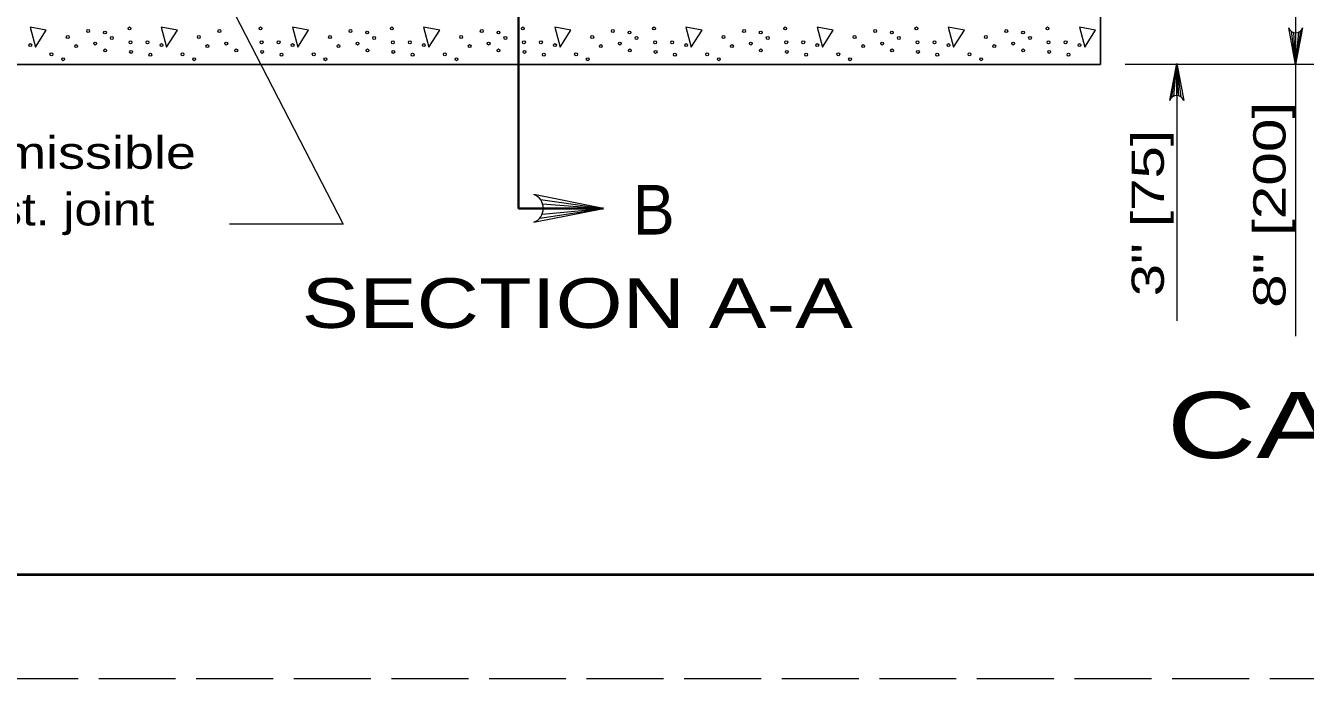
# Model space of a CAD drawing. Extents: x 1329.9 to 1363.9, y 715.5 to 737.5.
# Drawn here: x 1333.29 to 1339.48, y 715.5 to 718.65 of the extents above; entities that cross this region are included whole.
import ezdxf
from ezdxf.enums import TextEntityAlignment as Align

# ---------------------------------------------------------------- set-up
doc = ezdxf.new("R2010")
doc.units = 0
doc.header["$LTSCALE"] = 0.062
doc.linetypes.add('LONG_DASHED', pattern=[7.5, 6, -1.5])
doc.layers.add('1', color=7, linetype='Continuous', lineweight=13)

msp = doc.modelspace()

# ---------------------------------------------------------------- linework, layer by layer
at = {"layer": '1', "lineweight": 25}
for p, q in [((1338.4845, 718.46475), (1338.4845, 722.27233)), ((1332.86792, 718.46475), (1338.4845, 718.46475))]:
    msp.add_line(p, q, dxfattribs=at)
at = {"layer": '1', "lineweight": 35}
for p in [(1335.66942, 720.78442), (1336.08058, 717.76983)]:
    msp.add_line(p, (1335.66942, 717.76983), dxfattribs=at)
at = {"layer": '1'}
for p, q in [((1339.42875, 719.1235), (1339.42875, 717.1515)), ((1339.40742, 718.626), (1339.42875, 718.46475)), ((1339.41792, 718.6205), (1339.42875, 718.46475)), ((1339.45225, 718.62783), (1339.42875, 718.46475)), ((1339.44242, 718.62167), (1339.42875, 718.46475)), ((1339.42875, 718.61883), (1339.42875, 718.46475)), ((1340.42842, 718.46475), (1338.60475, 718.46475)), ((1338.83033, 718.30683), (1338.85383, 718.47)), ((1338.84017, 718.313), (1338.85383, 718.47)), ((1338.85383, 718.47), (1338.85383, 717.22583)), ((1338.85383, 718.31583), (1338.85383, 718.47)), ((1338.86458, 718.31417), (1338.85383, 718.47)), ((1338.87517, 718.30875), (1338.85383, 718.47)), ((1335.77242, 717.72275), (1336.08058, 717.76983)), ((1335.776, 717.8125), (1336.08058, 717.76983)), ((1335.78408, 717.7425), (1336.08058, 717.76983)), ((1335.78633, 717.79142), (1336.08058, 717.76983)), ((1335.7895, 717.76983), (1336.08058, 717.76983))]:
    msp.add_line(p, q, dxfattribs=at)
at = {"layer": '1', "linetype": 'LONG_DASHED'}
msp.add_lwpolyline([(1329.86333, 715.4975), (1363.86333, 715.4975), (1363.86333, 737.4975), (1329.86333, 737.4975)], close=True, dxfattribs=at)
at = {"layer": '1', "lineweight": 25}
msp.add_lwpolyline([(1363.36333, 715.9975), (1331.86333, 715.9975), (1331.86333, 736.9975)], dxfattribs=at)
at = {"layer": '1', "lineweight": 40}
msp.add_lwpolyline([(1331.86333, 736.9975), (1363.36333, 736.9975), (1363.36333, 715.9975), (1331.86333, 715.9975)], close=True, dxfattribs=at)
msp.add_lwpolyline([(1331.86333, 736.9975), (1363.36333, 736.9975), (1363.36333, 715.9975), (1331.86333, 715.9975)], close=True, dxfattribs=at)
at = {"layer": '1'}
for points in [[(1334.08708, 719.11958), (1334.82208, 717.69408), (1334.27158, 717.69408)], [(1339.46233, 718.64283), (1339.42875, 718.46475), (1339.39508, 718.64283)], [(1338.82025, 718.29183), (1338.85383, 718.47), (1338.8875, 718.29183)], [(1335.74417, 717.70258), (1336.08058, 717.76983), (1335.74417, 717.83717)]]:
    msp.add_lwpolyline(points, dxfattribs=at)
for points in [[(1333.30758, 718.64667), (1333.33325, 718.54925), (1333.3855, 718.63142)], [(1333.94208, 718.64667), (1333.96767, 718.54925), (1334.01992, 718.63142)], [(1334.57642, 718.64667), (1334.60208, 718.54925), (1334.65433, 718.63142)], [(1335.21083, 718.64667), (1335.23642, 718.54925), (1335.28867, 718.63142)], [(1335.84525, 718.64667), (1335.87092, 718.54925), (1335.92308, 718.63142)], [(1336.47967, 718.64667), (1336.50525, 718.54925), (1336.5575, 718.63142)], [(1337.114, 718.64667), (1337.13967, 718.54925), (1337.19192, 718.63142)], [(1337.74842, 718.64667), (1337.774, 718.54925), (1337.82633, 718.63142)], [(1338.38283, 718.64667), (1338.4085, 718.54925), (1338.46067, 718.63142)]]:
    msp.add_lwpolyline(points, close=True, dxfattribs=at)
msp.add_arc((1335.717, 717.76992), 0.07261, 292.08605, 67.91218, dxfattribs=at)
for centre in [(1333.58861, 718.62726), (1333.78792, 718.63991), (1334.22301, 718.62726), (1334.42232, 718.63991), (1334.85741, 718.62726), (1335.05672, 718.63991), (1335.49181, 718.62726), (1335.69111, 718.63991), (1336.12621, 718.62726), (1336.32551, 718.63991), (1336.7606, 718.62726), (1336.95991, 718.63991), (1337.395, 718.62726), (1337.59431, 718.63991), (1338.0294, 718.62726), (1338.22871, 718.63991), (1333.48927, 718.59821), (1333.62202, 718.56647), (1333.66944, 718.62026), (1333.70312, 718.59368), (1333.79305, 718.5728), (1333.87531, 718.5728), (1334.12367, 718.59821), (1334.25642, 718.56647), (1334.42744, 718.5728), (1334.50971, 718.5728), (1334.75807, 718.59821), (1334.89082, 718.56647), (1334.93824, 718.62026), (1334.97192, 718.59368), (1335.06184, 718.5728), (1335.1441, 718.5728), (1335.39247, 718.59821), (1335.52522, 718.56647), (1335.57264, 718.62026), (1335.60632, 718.59368), (1335.69624, 718.5728), (1335.7785, 718.5728), (1336.02687, 718.59821), (1336.15962, 718.56647), (1336.20704, 718.62026), (1336.24071, 718.59368), (1336.33064, 718.5728), (1336.4129, 718.5728), (1336.66127, 718.59821), (1336.79402, 718.56647), (1336.84144, 718.62026), (1336.87511, 718.59368), (1336.96504, 718.5728), (1337.0473, 718.5728), (1337.29567, 718.59821), (1337.42841, 718.56647), (1337.47584, 718.62026), (1337.50951, 718.59368), (1337.59944, 718.5728), (1337.6817, 718.5728), (1337.93007, 718.59821), (1338.06281, 718.56647), (1338.11024, 718.62026), (1338.14391, 718.59368), (1338.23384, 718.5728), (1338.3161, 718.5728), (1333.30852, 718.5592), (1333.41045, 718.51476), (1333.5304, 718.55467), (1333.67029, 718.53351), (1333.79558, 718.52657), (1333.889, 718.51297), (1333.94292, 718.5592), (1334.04485, 718.51476), (1334.1648, 718.55467), (1334.30469, 718.53351), (1334.42998, 718.52657), (1334.5234, 718.51297), (1334.57732, 718.5592), (1334.67925, 718.51476), (1334.7992, 718.55467), (1334.93909, 718.53351), (1335.06438, 718.52657), (1335.1578, 718.51297), (1335.21172, 718.5592), (1335.31365, 718.51476), (1335.4336, 718.55467), (1335.57349, 718.53351), (1335.69878, 718.52657), (1335.79219, 718.51297), (1335.84612, 718.5592), (1335.94805, 718.51476), (1336.068, 718.55467), (1336.20788, 718.53351), (1336.33318, 718.52657), (1336.42659, 718.51297), (1336.48052, 718.5592), (1336.58244, 718.51476), (1336.7024, 718.55467), (1336.84228, 718.53351), (1336.96758, 718.52657), (1337.06099, 718.51297), (1337.11492, 718.5592), (1337.21684, 718.51476), (1337.3368, 718.55467), (1337.47668, 718.53351), (1337.60198, 718.52657), (1337.69539, 718.51297), (1337.74932, 718.5592), (1337.85124, 718.51476), (1337.9712, 718.55467), (1338.11108, 718.53351), (1338.23637, 718.52657), (1338.32979, 718.51297), (1338.38371, 718.5592), (1333.46697, 718.49119), (1334.10136, 718.49119), (1334.73576, 718.49119), (1335.37016, 718.49119), (1336.00456, 718.49119), (1336.63896, 718.49119), (1337.27336, 718.49119), (1337.90776, 718.49119)]:
    msp.add_ellipse(centre, major_axis=(0, 0.00718), ratio=0.944544, dxfattribs=at)
for centre, major_axis in [((1339.42872, 718.65729), (0, -0.03844)), ((1338.85386, 718.27741), (0, 0.03844))]:
    msp.add_ellipse(centre, major_axis=major_axis, ratio=0.944544, start_param=5.0978942, end_param=7.4685073, dxfattribs=at)

# ---------------------------------------------------------------- texts
for s, width, p in [('8" [200]', 1.4, (1339.37983, 717.78704)), ('3" [75]', 1.35, (1338.79133, 717.74704))]:
    msp.add_text(s, height=0.156, rotation=90, dxfattribs=dict(at, width=width)).set_placement(p, align=Align.CENTER)
for s, height, width, p in [('Permissible', 0.156, 1.25, (1332.76183, 717.96133)), ('const. joint', 0.156, 1.15, (1332.76183, 717.68725)), ('SECTION A-A', 0.24, 1.3, (1334.6205, 717.192))]:
    msp.add_text(s, height=height, dxfattribs=dict(at, width=width)).set_placement(p)
for s, height, width, p in [('B', 0.24, 0.95, (1336.32375, 717.64342)), ('CATCH BASINS No. 2-5 & No. 2-6', 0.32, 1.4, (1343.43337, 716.56258))]:
    msp.add_text(s, height=height, dxfattribs=dict(at, width=width)).set_placement(p, align=Align.CENTER)

doc.saveas('drawing.dxf')
